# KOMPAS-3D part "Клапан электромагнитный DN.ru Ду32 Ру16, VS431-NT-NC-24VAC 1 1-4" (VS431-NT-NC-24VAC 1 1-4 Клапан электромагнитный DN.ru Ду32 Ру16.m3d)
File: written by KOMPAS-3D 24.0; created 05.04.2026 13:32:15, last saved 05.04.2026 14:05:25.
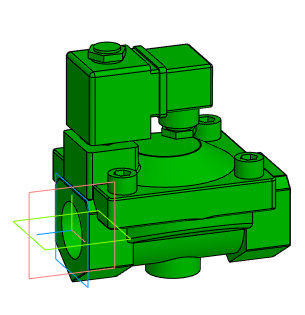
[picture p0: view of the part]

Document properties: Автор: artio; Полное имя файла: C:\Users\artio\OneDrive\Рабочий стол\Клапан электромагнитный DN.ru\VS431\VS431-NT-NC\VS431-NT-NC-24VAC\Ду32\VS431-NT-NC-24VAC 1 1-4 Клапан электромагнитный DN.ru Ду32 Ру16.m3d

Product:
- Body: Тело 1  | qty 1
    Масса: 3.709873
- Part/product: Клапан электромагнитный DN.ru Ду32 Ру16  | designation VS431-NT-NC-24VAC 1 1-4
    Масса: 1.701
    Раздел спецификации: Прочие изделия
    Примечание: D130-05510
    additional columns: ef56311e-7521-43dc-8291-0e6108b3d81d; artio; c; Шероховатость не задана; Да

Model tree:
1. Операция без истории:1

Expressions: VS431-NT-NC-24VAC 1 1-4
